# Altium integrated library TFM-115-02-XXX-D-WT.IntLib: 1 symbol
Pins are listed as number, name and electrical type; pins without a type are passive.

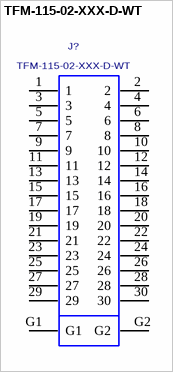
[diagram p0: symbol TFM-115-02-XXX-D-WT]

## TFM-115-02-XXX-D-WT
designator J?
0.050" TERMINAL STRIP, SURFACE MOUNT ASSEMBLY.; MANUFACTURER: SAMTEC
footprint TFM-115-02-XXX-D-WT
pins: 1, 2, 3, 4, 5, 6, 7, 8, 9, 10, 11, 12, 13, 14, 15, 16, 17, 18, 19, 20, 21, 22, 23, 24, 25, 26, 27, 28, 29, 30, G1, G2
